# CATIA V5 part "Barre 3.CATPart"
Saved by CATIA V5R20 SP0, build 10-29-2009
Part number: Barre 2
Bounding box of the stored display mesh (mm): x 37.661 to 75.254, y -2.339 to 75.254, z 0 to 2.5
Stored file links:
  C:\Users\Admin\Desktop\IAO\Barre 3.CATPart
  C:\Users\Admin\Desktop\IAO\Ass_4barres.CATProduct
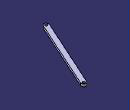
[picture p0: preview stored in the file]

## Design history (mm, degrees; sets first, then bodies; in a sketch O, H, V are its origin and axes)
Set1
  Sketch1 on Plane1, origin (0, 0, 0), H (1, 0, 0), V (0, 1, 0)
    construction line L1 (72.915, 72.915) -> (40, 0)
    point P1 (40, 0)
    point P2 (72.915, 72.915)
    line L2 (75.1936, 71.8864) -> (42.2786, -1.0286)
    line L3 (37.7214, 1.0286) -> (70.6364, 73.9436)
    arc A1 centre (40, 0) radius 2.5 from (42.2786, -1.0286) to (37.7214, 1.0286) cw
    arc A2 centre (72.915, 72.915) radius 2.5 from (70.6364, 73.9436) to (75.1936, 71.8864) cw
    reference projected point E1 (72.915, 72.915) from Point1
    reference projected point E2 (40, 0) from Point2
    distance L1 L2 = 2.5
    coincidence: P1 H, P2 E1, P1 E2
    tangency: A1 L2, A2 L2, A1 L3, A2 L3
Set2
  Plane1 "Plan ref": linked copy from another document
  Point1 "Point C": linked copy from another document
  Point2 "Point D": linked copy from another document
  Point3 "Point A": linked copy from another document
Body1 (main body)
  Pad1: profile Sketch1, direction (0, 0, 1), length 2.5
  Sketch2 on end face of Pad1, origin (72.8203, 69.8567, 2.5), H (1, 0, 0), V (0, 1, 0)
    point P1 (0.0948, 3.0583)
    reference projected arc E1 centre (0.0948, 3.0583) radius 2.5 from (2.3734, 2.0297) to (-2.1838, 4.0869) ccw from edge [face of Pad1 from Sketch1.A2 | end face of Pad1]
    concentricity: P1 E1
  Hole1: placed by Sketch2, at (72.915, 72.915, 2.5) direction (0, 0, -1), diameter 2.5, through (limit type 6)
  Sketch3 on end face of Pad1, origin (42.0551, 1.7676, 2.5), H (1, 0, 0), V (0, 1, 0)
    point P1 (-2.0551, -1.7676)
    reference projected arc E1 centre (-2.0551, -1.7676) radius 2.5 from (-4.3337, -0.739) to (0.2235, -2.7961) ccw from edge [face of Pad1 from Sketch1.A1 | end face of Pad1]
    concentricity: P1 E1
  Hole2: placed by Sketch3, at (40, 0, 2.5) direction (0, 0, -1), diameter 2.5, through (limit type 6)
